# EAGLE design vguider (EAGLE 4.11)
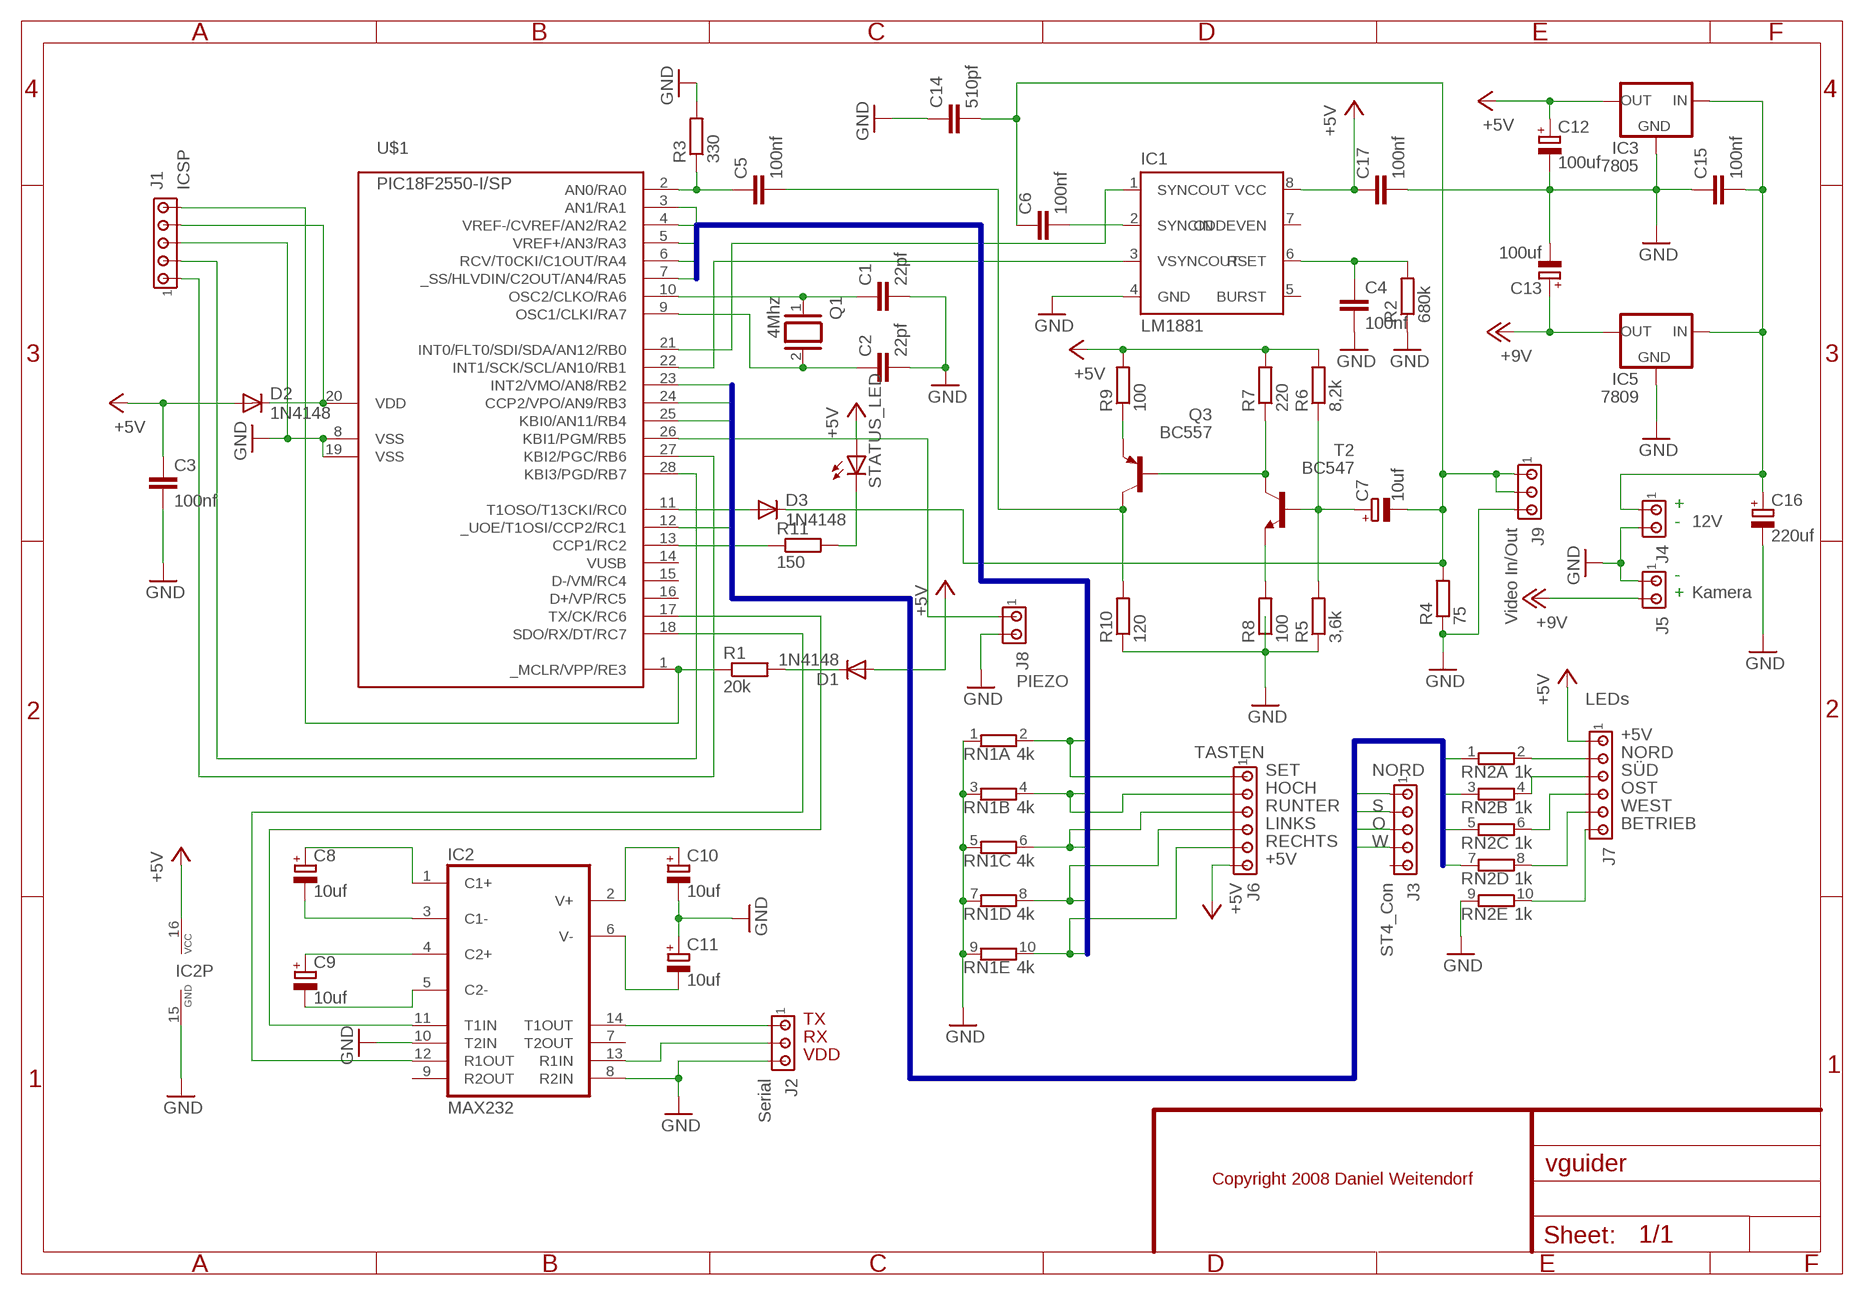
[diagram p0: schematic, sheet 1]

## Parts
C1  22pf  C2.5/2  [C2.5-2]
C2  22pf  C2.5/2  [C2.5-2]
C3  100nf  C5/2.5  [C5B2.5]
C4  100nf  C5/2.5  [C5B2.5]
C5  100nf  C5/2.5  [C5B2.5]
C6  100nf  C5/2.5  [C5B2.5]
C7  10uf  CPOL-EUE2,5-6E  [E2,5-6E]
C8  10uf  CPOL-EUE2.5-6  [E2,5-6]
C9  10uf  CPOL-EUE2.5-6  [E2,5-6]
C10  10uf  CPOL-EUE2.5-6  [E2,5-6]
C11  10uf  CPOL-EUE2.5-6  [E2,5-6]
C12  100uf  CPOL-EUE2.5-7  [E2,5-7]
C13  100uf  CPOL-EUE2.5-7  [E2,5-7]
C14  510pf  C5/2.5  [C5B2.5]
C15  100nf  C5/2.5  [C5B2.5]
C16  220uf  CPOL-EUE2.5-7  [E2,5-7]
C17  100nf  C5/2.5  [C5B2.5]
D1  1N4148  1N4004  [DO41-10]
D2  1N4148  1N4004  [DO41-10]
D3  1N4148  [DO35-10]
IC1  LM1881  [DIL08]
IC2  MAX232  [DIL16]
IC3  7805  78XXL  [78XXL]
IC5  7809  78XXL  [78XXL]
J1  ICSP  MTA05-100  [10X05MTA]
J2  Serial  MTA03-100  [10X03MTA]
J3  ST4_Con  MTA05-100  [10X05MTA]
J4  MTA02-156  [1X2MTA]
J5  MTA02-156  [1X2MTA]
J6  MTA06-100  [10X06MTA]
J7  MTA06-100  [10X06MTA]
J8  MTA02-100  [10X02MTA]
J9  Video In/Out  MTA03-100  [10X03MTA]
Q1  4Mhz  XTAL  [Q]
Q3  BC557  [TO92]
R1  20k  R-EU_0207/10  [0207/10]
R2  680k  R-EU_0207/10  [0207/10]
R3  330  R-EU_0207/10  [0207/10]
R4  75  R-EU_0207/12  [0207/12]
R5  3,6k  R-EU_0207/10  [0207/10]
R6  8,2k  R-EU_0207/10  [0207/10]
R7  220  R-EU_0207/10  [0207/10]
R8  100  R-EU_0207/10  [0207/10]
R9  100  R-EU_0207/10  [0207/10]
R10  120  R-EU_0207/10  [0207/10]
R11  150  R-EU_0207/10  [0207/10]
RN1  4k  E5R  [SIL10]
RN2  1k  E5R  [SIL10]
STATUS_LED  LED5MM  [LED5MM]
T2  BC547  [TO92]
U$1  PIC18F2550-I/SP  [DIL28-3]

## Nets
+5V: C3.1 C12.+ C17.1 D1.A D2.A IC1.8(VCC) IC2.16(VCC) IC3.OUT J6.1 J7.6 R6.2 R7.2 R9.2 STATUS_LED.A
+12V: C13.+ IC5.OUT J5.2 ; supply symbol labelled +9V
A0: J6.6 RN1.2 U$1.3(AN1/RA1)
A1: J6.5 RN1.4 U$1.4(VREF-/CVREF/AN2/RA2)
A2: J6.4 RN1.6 U$1.5(VREF+/AN3/RA3)
A3: J6.3 RN1.8 U$1.6(RCV/T0CKI/C1OUT/RA4)
A4: J6.2 RN1.10 U$1.7(_SS/HLVDIN/C2OUT/AN4/RA5)
GND: C1.2 C2.2 C3.2 C4.2 C10.- C11.+ C12.- C13.- C14.1 C15.1 C16.- C17.2 IC1.4(GND) IC2.8(R2IN) IC2.10(T2IN) IC2.15(GND) IC3.GND IC5.GND J1.3 J2.3 J4.2 J5.1 J8.2 J9.3 R2.1 R3.2 R4.1 R5.1 R8.1 R10.1 RN1.1 RN1.3 RN1.5 RN1.7 RN1.9 RN2.9 U$1.8(VSS) U$1.19(VSS)
N$1: C1.1 Q1.1 U$1.10(OSC2/CLKO/RA6)
N$2: C2.1 Q1.2 U$1.9(OSC1/CLKI/RA7)
N$3: J1.5 R1.1 U$1.1(_MCLR/VPP/RE3)
N$4: D1.C R1.2
N$5: D2.C J1.4 U$1.20(VDD)
N$6: IC1.1(SYNCOUT) U$1.21(INT0/FLT0/SDI/SDA/AN12/RB0)
N$7: IC1.3(VSYNCOUT) U$1.22(INT1/SCK/SCL/AN10/RB1)
N$8: J1.2 U$1.28(KBI3/PGD/RB7)
N$9: J1.1 U$1.27(KBI2/PGC/RB6)
N$10: C4.1 IC1.6(RSET) R2.2
N$11: C5.1 R3.1 U$1.2(AN0/RA0)
N$12: C6.2 IC1.2(SYNCIN)
N$13: C6.1 C7.- C14.2 D3.C J9.1 J9.2 R4.2
N$14: C7.+ R5.2 R6.1 T2.2(B)
N$15: Q3.2(B) R7.1 T2.3(C)
N$16: C5.2 Q3.3(C) R10.2
N$17: R8.2 T2.1(E)
N$18: Q3.1(E) R9.1
N$19: C15.2 C16.+ IC3.IN IC5.IN J4.1
N$20: C8.- IC2.3(C1-)
N$21: C8.+ IC2.1(C1+)
N$22: C9.+ IC2.4(C2+)
N$23: C9.- IC2.5(C2-)
N$24: C10.+ IC2.2(V+)
N$25: D3.A U$1.11(T1OSO/T13CKI/RC0)
N$26: C11.- IC2.6(V-)
N$27: IC2.14(T1OUT) J2.1
N$28: IC2.13(R1IN) J2.2
N$29: R11.1 U$1.13(CCP1/RC2)
N$30: R11.2 STATUS_LED.K(C)
N$31: IC2.12(R1OUT) U$1.18(SDO/RX/DT/RC7)
N$32: IC2.11(T1IN) U$1.17(TX/CK/RC6)
N$33: J7.5 RN2.2
N$34: J7.4 RN2.4
N$35: J7.3 RN2.6
N$36: J7.2 RN2.8
N$37: J7.1 RN2.10
N$38: J8.1 U$1.26(KBI1/PGM/RB5)
NORD: J3.1 RN2.1 U$1.23(INT2/VMO/AN8/RB2)
OST: J3.3 RN2.5 U$1.25(KBI0/AN11/RB4)
SUED: J3.2 RN2.3 U$1.24(CCP2/VPO/AN9/RB3)
WEST: J3.4 RN2.7 U$1.12(_UOE/T1OSI/CCP2/RC1)
Unconnected: IC1.5(BURST) IC1.7(ODDEVEN) IC2.7(T2OUT) IC2.9(R2OUT) J3.5 U$1.14(VUSB) U$1.15(D-/VM/RC4) U$1.16(D+/VP/RC5)

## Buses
ATBUS:A[0..4]
ST4:NORD,SUED,OST,WEST

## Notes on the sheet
- +
- - | 12V
- -
- + | Kamera
- PIEZO
- LEDs
- +5V
- TASTEN | NORD
- SET | NORD | SÜD
- HOCH | OST
- RUNTER | S | WEST
- LINKS | O | BETRIEB
- RECHTS | W
- +5V
- TX
- RX
- VDD
- Copyright 2008 Daniel Weitendorf

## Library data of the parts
C1-C6 C14 C15 C17 = capacitor-wima:C: CAPACITOR
C7-C13 C16 = rcl:CPOL-EU: POLARIZED CAPACITOR, European symbol
D1 D2 = diode:1N4004: DIODE
D3 = diode:1N4148: DIODE
IC1 = lm1881:LM1881
IC2 = maxim:MAX232: RS232 TRANSEIVER
IC3 IC5 = v-reg:78XXL: VOLTAGE REGULATOR
J1 J3 = con-amp:MTA05-100: AMP connector
J2 J9 = con-amp:MTA03-100: AMP connector
J4 J5 = con-amp:MTA02-156: AMP connector
J6 J7 = con-amp:MTA06-100: AMP connector
J8 = con-amp:MTA02-100: AMP connector
Q1 = special:XTAL: CRYSTAL
Q3 = transistor-pnp:BC557: PNP Transistor
R1-R11 = rcl:R-EU_: RESISTOR, European symbol
RN1 RN2 = resistor-sil:E5R: SIL RESISTOR
STATUS_LED = led:LED: LED
T2 = transistor:BC547: NPN TRANSISTOR
U$1 = microchip-pic18fxx5x:PIC18*2550: PIC18*2550 Microchip FLASH Microcontroller with FS-USB DEVICE FEATURES FeaturePIC18*2550 Program Memory (bytes) 32k Program Memory (instructions) 16384 I/O Ports Ports A, B, C, (E) Capture/Compare/PWM Modules 2 Enhanced Capture/Compare/PWM Modules 0 Parallel Communications (PSP) No 10-bit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

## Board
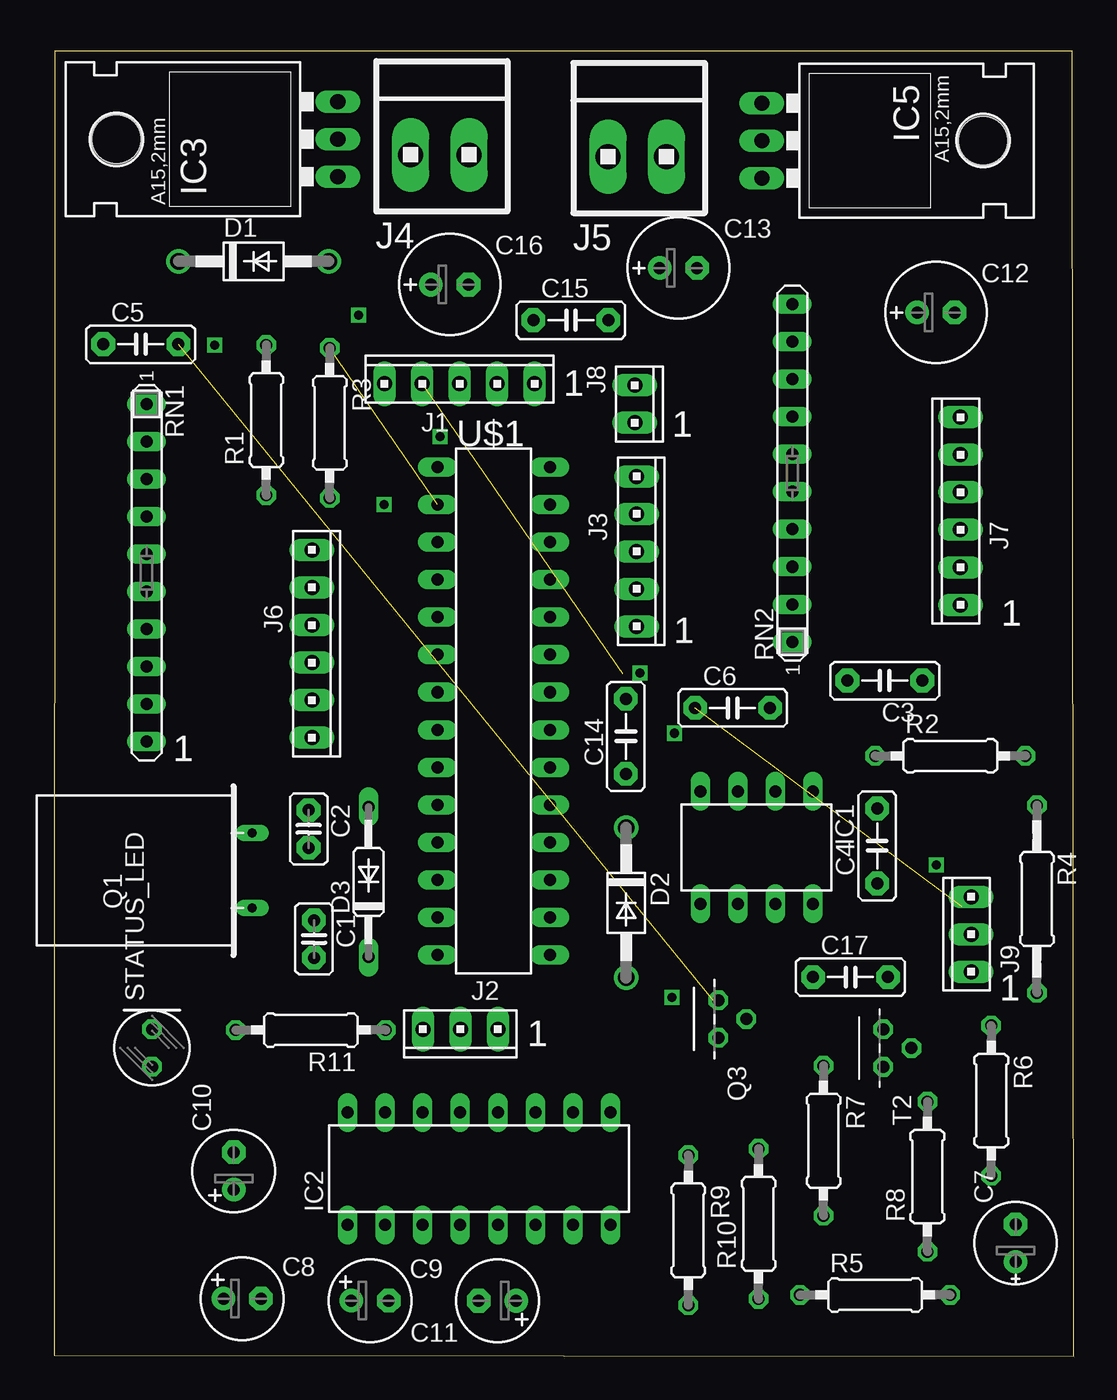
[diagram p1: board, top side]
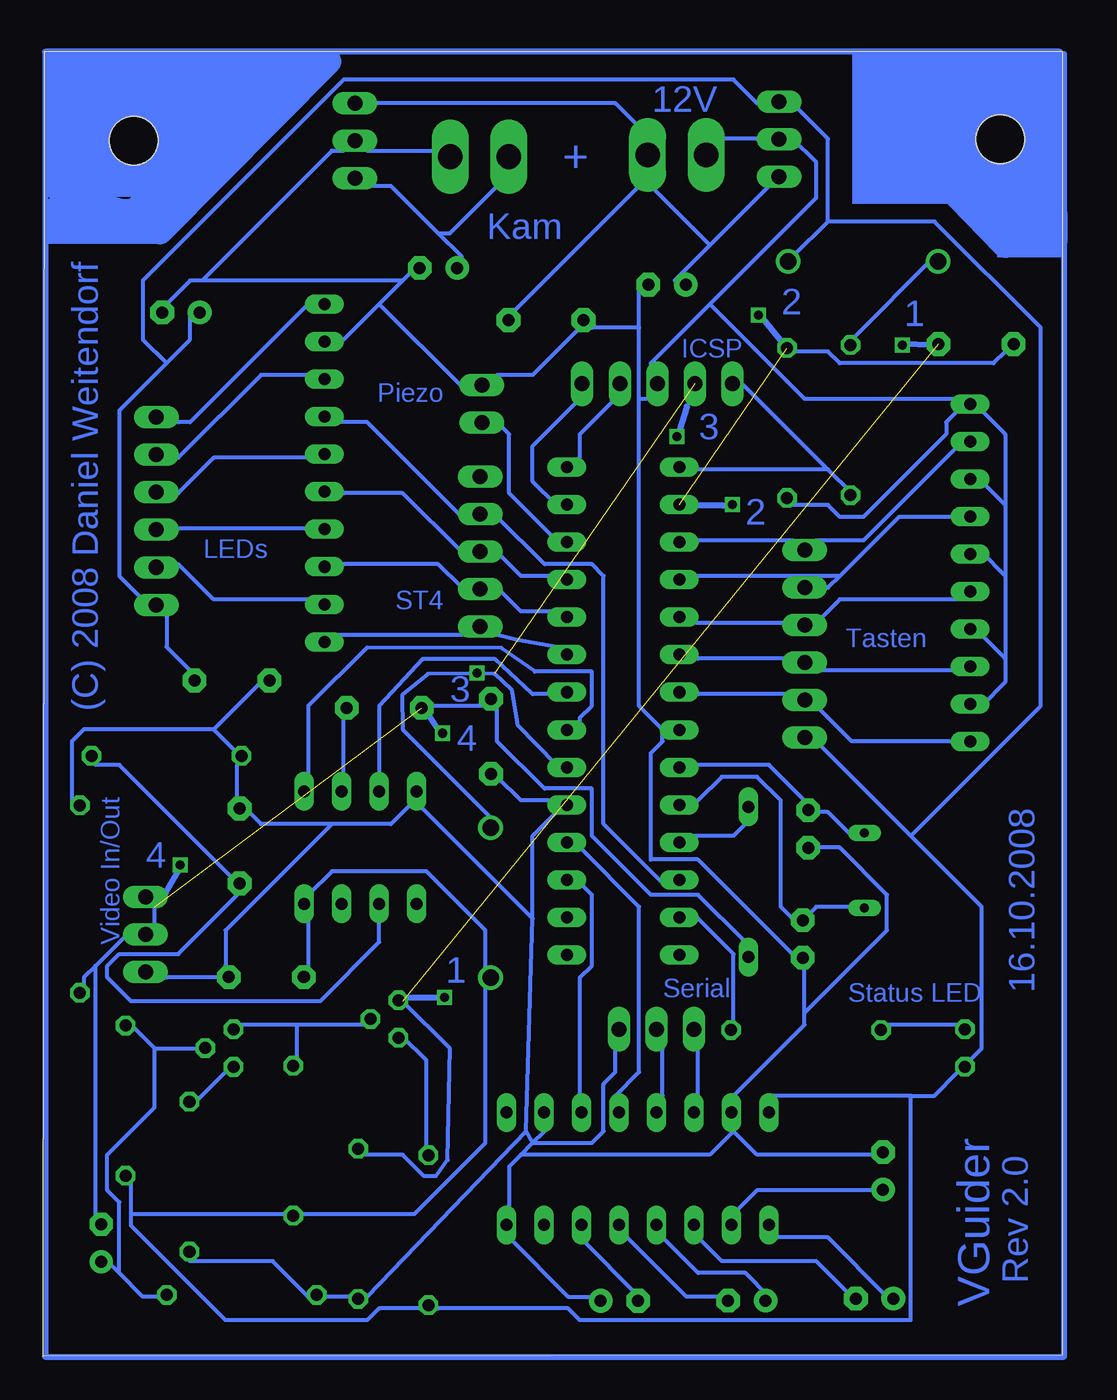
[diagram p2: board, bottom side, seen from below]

Size 69.02 x 88.38 mm. Coordinates in mm from the lower left corner, seen from the top.
Outline: 0,0.06 69.02,0 68.91,88.38 0.01,88.37 0,0.06
Copper layers 16: Bottom 0.035mm
Design rules "default": minimum track width 10mil, minimum drill 24mil, track to track 8mil, track to pad 8mil, pad to pad 8mil, via to via 8mil, smd to smd 8mil, copper to edge 40mil, drill to drill 8mil, minimum pad ring 10mil, minimum via ring 8mil, stop-mask expansion 4mil, vias tented up to drill 0mil, thermal gap 10mil

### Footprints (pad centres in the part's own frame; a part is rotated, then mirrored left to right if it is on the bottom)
C2.5-2 = drill 0.813 pad 1.6 octagon: 1 -1.27,0; 2 1.27,0
C5B2.5 = drill 0.813 pad 1.6 octagon: 1 -2.54,0; 2 2.54,0
E2,5-6E = drill 0.813 pad 1.575 round: + -1.27,0 | drill 0.813 pad 1.575 octagon: - 1.27,0
E2,5-6 = drill 0.813 pad 1.6 round: + -1.27,0 | drill 0.813 pad 1.6 octagon: - 1.27,0
E2,5-7 = drill 0.813 pad 1.6 round: + -1.27,0 | drill 0.813 pad 1.6 octagon: - 1.27,0
DO41-10 = drill 1.118 round: A 5.08,0; C -5.08,0
DO35-10 = drill 0.813 long: A 5.08,0; C -5.08,0
DIL08 = drill 0.813 long: 1 -3.81,-3.81; 2 -1.27,-3.81; 3 1.27,-3.81; 4 3.81,-3.81; 5 3.81,3.81; 6 1.27,3.81; 7 -1.27,3.81; 8 -3.81,3.81
DIL16 = drill 0.813 long: 1 -8.89,-3.81; 2 -6.35,-3.81; 3 -3.81,-3.81; 4 -1.27,-3.81; 5 1.27,-3.81; 6 3.81,-3.81; 7 6.35,-3.81; 8 8.89,-3.81; 9 8.89,3.81; 10 6.35,3.81; 11 3.81,3.81; 12 1.27,3.81; 13 -1.27,3.81; 14 -3.81,3.81; 15 -6.35,3.81; 16 -8.89,3.81
78XXL = drill 1.016 long: GND 0,-3.81; IN -2.54,-3.81; OUT 2.54,-3.81 | hole 3.302: 0,11.176
10X05MTA = drill 1.016 long: 1 5.08,0; 2 2.54,0; 3 0,0; 4 -2.54,0; 5 -5.08,0
10X03MTA = drill 1.016 long: 1 2.54,0; 2 0,0; 3 -2.54,0
1X2MTA = drill 1.676 long: 1 1.981,0; 2 -1.981,0
10X06MTA = drill 1.016 long: 1 6.35,0; 2 3.81,0; 3 1.27,0; 4 -1.27,0; 5 -3.81,0; 6 -6.35,0
10X02MTA = drill 1.016 long: 1 1.27,0; 2 -1.27,0
Q = drill 0.61 long: 1 -2.54,-7.62; 2 2.54,-7.62
TO92 = drill 0.813 octagon: 1 1.27,0; 2 0,1.905; 3 -1.27,0
0207/10 = drill 0.813 octagon: 1 -5.08,0; 2 5.08,0
0207/12 = drill 0.813 octagon: 1 -6.35,0; 2 6.35,0
SIL10 = drill 0.813 long: 1 -11.43,0; 2 -8.89,0; 3 -6.35,0; 4 -3.81,0; 5 -1.27,0; 6 1.27,0; 7 3.81,0; 8 6.35,0; 9 8.89,0; 10 11.43,0
LED5MM = drill 0.813 octagon: A -1.27,0; K 1.27,0
DIL28-3 = drill 0.813 long: 1 -16.51,-3.81; 2 -13.97,-3.81; 3 -11.43,-3.81; 4 -8.89,-3.81; 5 -6.35,-3.81; 6 -3.81,-3.81; 7 -1.27,-3.81; 8 1.27,-3.81; 9 3.81,-3.81; 10 6.35,-3.81; 11 8.89,-3.81; 12 11.43,-3.81; 13 13.97,-3.81; 14 16.51,-3.81; 15 16.51,3.81; 16 13.97,3.81; 17 11.43,3.81; 18 8.89,3.81; 19 6.35,3.81; 20 3.81,3.81; 21 1.27,3.81; 22 -1.27,3.81; 23 -3.81,3.81; 24 -6.35,3.81; 25 -8.89,3.81; 26 -11.43,3.81; 27 -13.97,3.81; 28 -16.51,3.81

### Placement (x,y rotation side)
C1  17.58,28.26 270 top
C2  17.21,35.71 270 top
C3  56.23,45.76 180 top
C4  55.71,34.56 90 top
C5  5.84,68.54 0 top
C6  45.92,43.91 0 top
C7  65.09,7.68 90 top
C8  12.72,3.91 0 top
C9  21.37,3.77 0 top
C10  12.14,12.55 90 top
C11  29.99,3.77 180 top
C12  59.69,70.68 0 top
C13  42.25,73.7 0 top
C14  38.69,41.98 90 top
C15  34.96,70.16 0 top
C16  26.77,72.57 0 top
C17  53.9,25.68 0 top
D1  13.49,74.15 0 top
D2  38.72,30.72 270 top
D3  21.27,32.13 90 top
IC1  47.55,34.46 180 top
IC2  28.75,12.71 0 top
IC3  15.38,82.41 90 top
IC5  51.71,82.32 270 top
J1  27.43,65.86 0 top
J2  27.48,22.14 180 top
J3  39.42,54.5 270 top
J4  26.1,81.35 0 top
J5  39.46,81.23 0 top
J6  17.44,48.25 270 top
J7  61.35,57.24 90 top
J8  39.3,64.49 270 top
J9  62.08,28.58 90 top
Q1  5.78,32.9 90 top
Q3  44.95,22.84 270 top
R1  14.34,63.4 90 top
R2  60.67,40.66 0 top
R3  18.64,63.2 270 top
R4  66.53,30.97 270 top
R5  55.57,4.16 0 top
R6  63.44,17.32 270 top
R7  52.08,14.6 270 top
R8  59.11,12.17 90 top
R9  42.92,8.54 270 top
R10  47.68,8.97 90 top
R11  17.36,22.09 180 top
RN1  6.23,53.06 270 top
RN2  49.97,59.81 90 top
STATUS_LED  6.6,20.89 90 top
T2  56.13,20.87 270 top
U$1  29.74,43.7 270 top

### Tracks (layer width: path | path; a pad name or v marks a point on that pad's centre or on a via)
+5V
  Bottom 0.254: C17.1 51.07,26.45 51.07,29.65 IC1.8 51.07,31.25 49.47,32.85 43.07,32.85 39.07,28.85 39.07,26.45 D2.A 39.07,24.85 39.07,14.45 43.87,9.65 51.87,9.65 R7.2 52.67,9.65 63.07,9.65 | 63.07,9.65 63.07,12.05 R6.2 | 63.07,9.65 63.07,8.85 56.67,2.45 47.07,2.45 46.27,3.25 43.07,3.25 R9.2 42.27,3.25 33.47,3.25 32.67,2.45 10.27,2.45 10.27,17.65 | C3.1 59.07,46.45 60.67,48.05 60.67,50.45 J7.6 62.27,51.25 63.87,52.85 63.87,64.05 60.67,67.25 | 60.67,67.25 59.07,68.85 59.07,70.45 C12.+ | 15.87,76.85 15.87,82.45 18.27,84.85 IC3.OUT 20.67,84.85 22.27,86.45 48.67,86.45 62.27,72.85 62.27,68.85 60.67,67.25 | 15.87,76.85 18.27,74.45 D1.A | 10.27,17.65 8.67,17.65 7.07,19.25 STATUS_LED.A 6.27,20.05 5.47,20.85 5.47,30.45 10.27,35.25 | 10.27,17.65 19.87,17.65 IC2.16 | 10.27,35.25 16.67,41.65 J6.1 | 15.87,76.85 8.67,76.85 1.47,69.65 1.47,44.05 10.27,35.25
+12V
  Bottom 0.254: 42.27,76.05 40.67,74.45 C13.+ | 42.27,76.05 45.47,79.25 47.07,79.25 IC5.OUT | 42.27,76.05 41.47,76.05 38.27,79.25 J5.2
A0
  Bottom 0.254: RN1.2 7.07,61.65 13.47,55.25 16.67,55.25 J6.6 18.27,55.25 24.67,55.25 U$1.3
A1
  Bottom 0.254: 15.07,52.85 15.87,52.05 16.67,52.05 J6.5 | 15.07,52.85 11.07,56.85 7.07,56.85 RN1.4 | 15.07,52.85 24.67,52.85 U$1.4
A2
  Bottom 0.254: RN1.6 7.07,51.25 15.07,51.25 16.67,49.65 J6.4 18.27,49.65 25.47,49.65 U$1.5
A3
  Bottom 0.254: RN1.8 7.07,46.45 16.67,46.45 J6.3 18.27,47.25 24.67,47.25 U$1.6
A4
  Bottom 0.254: RN1.10 7.07,41.65 14.27,41.65 16.67,44.05 J6.2 18.27,44.85 24.67,44.85 U$1.7
GND
  Bottom 0.254: J5.1 42.27,81.65 47.07,81.65 IC5.GND 48.67,81.65 49.47,81.65 58.27,72.85 | 44.67,72.85 43.87,73.65 C13.- | 46.27,71.25 44.67,72.85 | 46.27,71.25 48.67,68.85 RN2.9 | 46.27,71.25 40.67,65.65 J8.2 38.27,66.45 35.87,66.45 32.67,69.65 C15.1 31.87,69.65 28.67,69.65 | 44.67,72.85 58.27,72.85 | 58.27,72.85 59.07,72.85 60.67,71.25 C12.- | 3.87,47.25 3.87,45.65 5.47,44.05 RN1.9 | 3.87,47.25 5.47,48.85 RN1.7 | 3.87,52.85 5.47,54.45 RN1.5 | 3.87,52.85 3.87,47.25 | 3.87,57.65 5.47,59.25 RN1.3 | 3.87,57.65 3.87,52.85 | 3.87,57.65 3.87,62.45 5.47,64.05 RN1.1 | R3.2 18.27,57.65 15.87,57.65 15.07,56.85 13.47,56.85 7.87,62.45 7.87,63.25 7.07,64.05 RN1.1 | J4.2 23.07,82.45 20.67,82.45 IC3.GND 18.27,82.45 16.67,80.85 16.67,78.45 23.87,71.25 | 27.07,42.45 28.67,44.05 28.67,64.85 | 28.67,69.65 28.67,72.85 C16.- | 28.67,64.85 28.67,69.65 | 28.67,64.85 27.87,64.85 J1.3 27.87,67.25 23.87,71.25 | 23.87,71.25 17.47,64.85 7.07,64.85 RN1.1 | J9.3 60.67,25.65 56.67,25.65 C17.2 56.67,26.45 56.67,28.85 49.47,36.05 | 43.87,37.65 45.47,36.05 49.47,36.05 | 49.47,36.05 54.27,36.05 55.07,36.85 C4.2 55.87,37.65 55.87,40.05 R2.1 55.87,40.85 57.47,42.45 | 57.47,42.45 66.27,42.45 67.07,41.65 67.07,37.65 R4.1 | 57.47,42.45 54.27,45.65 C3.2 | 22.27,15.25 20.67,13.65 12.67,13.65 C10.- | 17.47,23.25 17.47,22.45 22.27,17.65 IC2.15 22.27,15.25 | 17.47,23.25 17.47,26.45 C1.2 18.27,27.25 24.67,33.65 27.87,33.65 27.87,40.85 27.07,41.65 27.07,42.45 | 17.47,23.25 11.87,28.85 11.87,31.25 15.07,34.45 16.67,34.45 C2.2 | R8.1 59.07,6.45 53.47,6.45 51.07,4.05 R5.1 50.27,4.05 47.87,4.05 R10.1 47.07,4.05 36.32,15.25 | C14.1 38.27,39.25 36.67,37.65 34.27,37.65 U$1.19 34.27,36.85 35.87,35.25 35.87,29.65
  Bottom 0.254: 35.87,14.45 35.07,15.25 IC2.10 | 36.67,13.65 35.87,14.45 | 36.67,13.65 37.47,12.85 37.47,9.65 IC2.8 37.47,8.05 33.47,4.05 31.87,4.05 C11.+ | 35.87,14.45 31.87,14.45 31.07,15.25 31.07,18.45 30.27,19.25 30.27,20.85 J2.3 | 35.87,14.45 36.32,15.25 | 36.32,15.25 35.87,29.65 | 22.27,15.25 23.87,13.65 36.67,13.65 | 35.87,29.65 43.87,37.65 | 43.87,37.65 IC1.4 | 27.07,42.45 U$1.8
N$1
  Bottom 0.254: Q1.1 14.27,30.45 16.67,30.45 17.47,29.65 C1.1 18.27,29.65 19.07,30.45 19.07,37.65 20.67,39.25 23.07,39.25 24.67,37.65 U$1.10
N$2
  Bottom 0.254: Q1.2 14.27,35.25 15.87,36.85 16.67,36.85 C2.1 17.47,37.65 19.87,40.05 24.67,40.05 U$1.9
N$3
  Bottom 0.254: 15.87,60.05 22.27,66.45 J1.5 | 15.87,60.05 14.27,58.45 R1.1 | 15.87,60.05 24.67,60.05 U$1.1
N$4
  Bottom 0.254: R1.2 14.27,68.85 8.67,74.45 D1.C
N$5  (1 unrouted)
  Bottom 0.254: U$1.20 34.27,40.05 36.86,42.72 37.28,45.12 38.46,46.22 42.95,46.22 44.7,44.77 44.67,42.45 38.27,36.05 D2.C
N$6
  Bottom 0.254: U$1.21 32.67,42.45 32.67,43.25 31.87,44.05 31.87,46.37 35.72,46.37 38,47.97 47.07,47.98 51.07,44.05 51.07,39.25 IC1.1
N$7
  Bottom 0.254: IC1.3 46.27,39.25 46.27,44.05 43.32,47.21 38.42,47.21 35.87,44.85 34.27,44.85 U$1.22
N$8
  Bottom 0.254: U$1.28 32.67,60.85 32.67,62.45 30.27,64.85 J1.2
N$9
  Bottom 0.254: U$1.27 34.27,57.65 35.87,59.25 35.87,61.65 32.67,64.85 J1.1
N$10
  Bottom 0.254: IC1.6 46.27,29.65 46.27,28.05 50.27,24.05 63.07,24.05 64.67,25.65 64.67,26.45 63.87,27.25 59.87,27.25 55.87,31.25 C4.1 55.87,32.05 63.87,40.05 65.47,40.05 R2.2
N$11  (1 unrouted)
  Bottom 0.254: R3.1 18.27,68.05 15.87,68.05 15.07,67.25 4.67,67.25 3.87,68.05 C5.1
N$12
  Bottom 0.254: IC1.2 48.67,39.25 48.67,43.25 C6.2
N$13  (1 unrouted)
  Bottom 0.254: D3.C 21.47,28.05 24.67,31.25 27.87,31.25 31.87,35.25 31.87,38.45 35.07,38.45 38.27,41.65 38.27,44.05 C14.2 39.07,44.05 43.07,44.05 C6.1 | 65.47,26.45 63.07,28.85 J9.2 61.47,28.85 61.47,30.45 J9.1 | 65.47,26.45 66.27,25.65 66.27,24.85 R4.2 | 65.47,26.45 65.47,9.65 C7.-
N$14
  Bottom 0.254: 61.47,20.85 58.27,20.85 T2.2 | 61.47,20.85 63.07,22.45 R6.1 | 63.87,5.65 64.67,6.45 C7.+ | 63.87,5.65 62.27,4.05 60.67,4.05 R5.2 | 61.47,20.85 61.47,16.85 64.67,13.65 64.67,11.25 63.87,10.45 63.87,5.65
N$15
  Bottom 0.254: 51.87,22.45 55.87,22.45 T2.3 | 51.87,22.45 47.07,22.45 Q3.2 | 51.87,22.45 51.87,20.05 R7.1
N$16  (1 unrouted)
  Bottom 0.254: R10.2 47.87,13.65 44.67,13.65 43.22,12.2 42.42,12.2 41.62,13.3 41.47,20.85 44.67,24.05 Q3.3
N$17
  Bottom 0.254: T2.1 56.67,19.25 59.07,16.85 R8.2
N$18
  Bottom 0.254: R9.1 43.07,13.65 43.07,20.05 44.67,21.65 Q3.1
N$19
  Bottom 0.254: 23.87,75.25 26.27,72.85 C16.+ | 23.87,75.25 19.87,79.25 IC3.IN | IC5.IN 47.07,84.85 30.27,84.85 28.67,83.25 J4.1 | C15.2 37.47,70.45 28.67,79.25 J4.1 | 23.87,75.25 27.87,79.25 J4.1
N$20
  Bottom 0.254: IC2.3 24.67,8.05 23.07,6.45 16.67,6.45 14.27,4.05 C8.-
N$21
  Bottom 0.254: IC2.1 19.87,8.05 15.87,8.05 11.87,4.05 C8.+
N$22
  Bottom 0.254: IC2.4 27.07,8.05 24.67,5.65 21.47,5.65 19.87,4.05 C9.+
N$23
  Bottom 0.254: IC2.5 29.47,8.05 25.47,4.05 23.07,4.05 C9.-
N$24
  Bottom 0.254: IC2.2 22.27,9.65 20.67,11.25 12.67,11.25 C10.+
N$25
  Bottom 0.254: U$1.11 25.47,35.25 22.27,35.25 21.47,36.05 D3.A
N$26
  Bottom 0.254: IC2.6 32.67,8.05 28.67,4.05 C11.-
N$27
  Bottom 0.254: IC2.14 24.67,17.65 24.67,20.85 J2.1
N$28
  Bottom 0.254: IC2.13 27.07,17.65 27.07,20.85 J2.2
N$29
  Bottom 0.254: R11.1 22.27,22.45 22.27,27.25 24.67,29.65 U$1.13
N$30
  Bottom 0.254: STATUS_LED.K 7.07,22.45 11.87,22.45 R11.2
N$31
  Bottom 0.254: IC2.12 30.27,17.65 28.67,19.25 28.67,30.45 32.67,34.45 U$1.18
N$32
  Bottom 0.254: IC2.11 32.67,17.65 32.67,25.65 31.87,26.45 31.87,31.25 32.67,32.05 U$1.17
N$33
  Bottom 0.254: RN2.2 51.07,51.25 57.47,51.25 59.87,53.65 J7.5
N$34
  Bottom 0.254: RN2.4 51.07,56.05 59.87,56.05 J7.4
N$35
  Bottom 0.254: RN2.6 51.07,60.85 57.47,60.85 59.87,58.45 J7.3
N$36
  Bottom 0.254: RN2.8 51.07,66.45 54.27,66.45 59.87,60.85 J7.2
N$37
  Bottom 0.254: RN2.10 51.07,71.25 59.07,63.25 59.87,63.25 J7.1
N$38
  Bottom 0.254: U$1.26 34.27,55.25 37.47,58.45 37.47,62.45 38.27,63.25 J8.1
N$39
  Bottom 0.406: 0.17,88.33 68.88,88.33 68.88,-0.01 -0.13,-0.01 -0.13,88.18
N$40  (via drill 0.61)
  other vias: 39.63,46.27
N$41  (via drill 0.61)
  other vias: 26.11,62.28
N$42
  Bottom 0.406: 25.43,64.32 25.96,62.58
N$43  (via drill 0.61)
  other vias: 20.59,70.51
N$44
  Bottom 0.406: 18.93,68.62 20.29,70.28
N$45  (via drill 0.61)
  other vias: 22.33,57.67
N$46
  Bottom 0.406: 22.94,57.6 24.9,57.6
N$47  (via drill 0.61)
  Bottom 0.406: 8.96,68.47 10.7,68.55
  other vias: 10.85,68.47
N$48  (via drill 0.61)
  Bottom 0.406: 44.47,24.3 41.98,24.3
  other vias: 41.82,24.3
N$49  (via drill 0.61)
  other vias: 41.97,42.19
N$50
  Bottom 0.406: 42.28,42.5 42.88,43.4
N$51  (via drill 0.61)
  other vias: 59.73,33.28
N$52
  Bottom 0.406: 60.71,31.4 59.88,32.83
N$53
  Bottom 1.676: 51.32,87.27 61.66,76.23
N$54
  Bottom 1.676: 52.26,87.59 63.07,77.33 67.76,78.66
N$55
  Bottom 1.676: 61.11,76.15 49.67,87.67
N$56
  Bottom 1.676: 3.86,75.21 9.18,80.69 3.31,76.93
N$57
  Bottom 1.676: 0.49,75.52 0.57,87.67
N$58
  Bottom 1.676: 50.77,87.67 52.81,86.96
NORD
  Bottom 0.254: U$1.23 34.27,48.05 36.94,48.5 38.27,48.85 J3.1 40.67,48.85 49.47,48.85 RN2.1
OST
  Bottom 0.254: U$1.25 34.27,52.85 36.67,52.85 38.27,54.45 J3.3 40.67,54.45 44.67,58.45 48.67,58.45 RN2.5
SUED
  Bottom 0.254: U$1.24 34.27,50.45 36.67,50.45 38.27,52.05 J3.2 40.67,52.05 42.27,53.65 48.67,53.65 RN2.3
WEST
  Bottom 0.254: U$1.12 27.07,32.05 31.07,36.05 31.07,52.85 31.87,53.65 35.07,53.65 38.27,56.85 J3.4 40.67,56.85 47.07,63.25 49.47,63.25 RN2.7
(copper drawn outside any net)
  shapes: Bottom area x6

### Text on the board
Bottom: 12V | + | Kam | (C) 2008 Daniel Weitendorf | 1 | 2 | ICSP | Piezo | 3 | 2 | LEDs | ST4 | Tasten | 3 | 4 | Video In/Out | 16.10.2008 | 4 | 1 | Status LED | Serial | VGuider | Rev 2.0
tPlace: 1 | 1 | 1 | 1 | 1 | 1 | 1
